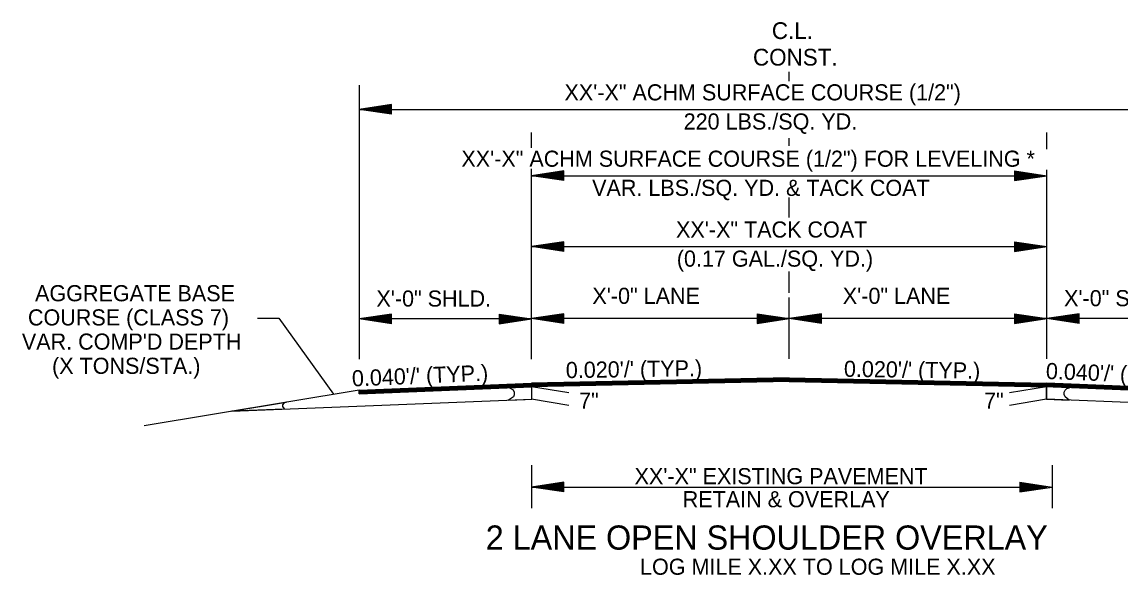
# Model space of a CAD drawing. Extents: x 542112 to 1930787, y -1968972 to 596640.
# Drawn here: x 546593 to 547104, y -1956850 to -1956593 of the extents above; entities that cross this region are included whole.
import ezdxf

# ---------------------------------------------------------------- set-up
doc = ezdxf.new("R2010")
doc.units = 0
doc.layers.add('R_Draft', color=7, linetype='Continuous')

msp = doc.modelspace()

# ---------------------------------------------------------------- linework, layer by layer
at = {"layer": 'R_Draft'}
for p, q in [((546950.47, -1956620.68), (546950.47, -1956616.27)), ((546750.21, -1956622.52), (546750.21, -1956749.95)), ((546765.21, -1956631.53), (546750.21, -1956633.78)), ((546765.21, -1956631.91), (546752.71, -1956633.78)), ((546765.21, -1956632.29), (546755.29, -1956633.78)), ((546765.21, -1956632.66), (546757.79, -1956633.78)), ((546765.21, -1956636.03), (546765.21, -1956631.53)), ((546750.21, -1956633.78), (547150.66, -1956633.78)), ((546765.21, -1956636.03), (546750.21, -1956633.78)), ((546765.21, -1956635.66), (546752.71, -1956633.78)), ((546765.21, -1956635.27), (546755.29, -1956633.78)), ((546765.21, -1956634.9), (546757.79, -1956633.78)), ((546765.21, -1956633.05), (546760.33, -1956633.78)), ((546765.21, -1956634.51), (546760.33, -1956633.78)), ((546765.21, -1956633.43), (546762.84, -1956633.78)), ((546765.21, -1956634.13), (546762.84, -1956633.78)), ((546830.47, -1956651.76), (546830.47, -1956644.62)), ((546950.47, -1956650.81), (546950.47, -1956647.14)), ((547070.4, -1956652.27), (547070.4, -1956644.62)), ((546830.47, -1956749.95), (546830.47, -1956661.53)), ((546845.47, -1956662.4), (546830.47, -1956664.65)), ((546845.47, -1956662.78), (546832.98, -1956664.65)), ((546845.47, -1956663.16), (546835.56, -1956664.65)), ((546845.47, -1956663.53), (546838.05, -1956664.65)), ((546845.47, -1956666.9), (546845.47, -1956662.4)), ((547055.4, -1956662.4), (547070.4, -1956664.65)), ((547055.4, -1956662.4), (547055.4, -1956666.9)), ((547055.4, -1956662.78), (547067.89, -1956664.65)), ((547055.4, -1956663.16), (547065.31, -1956664.65)), ((547055.4, -1956663.53), (547062.81, -1956664.65)), ((547070.4, -1956749.78), (547070.4, -1956661.94)), ((546830.47, -1956664.65), (547070.4, -1956664.65)), ((546845.47, -1956666.9), (546830.47, -1956664.65)), ((546845.47, -1956666.53), (546832.98, -1956664.65)), ((546845.47, -1956666.14), (546835.56, -1956664.65)), ((546845.47, -1956665.77), (546838.05, -1956664.65)), ((546845.47, -1956663.92), (546840.6, -1956664.65)), ((546845.47, -1956665.38), (546840.6, -1956664.65)), ((546845.47, -1956664.3), (546843.1, -1956664.65)), ((546845.47, -1956665), (546843.1, -1956664.65)), ((547055.4, -1956663.92), (547060.27, -1956664.65)), ((547055.4, -1956664.3), (547057.77, -1956664.65)), ((547055.4, -1956666.9), (547070.4, -1956664.65)), ((547055.4, -1956665.39), (547060.27, -1956664.65)), ((547055.4, -1956666.14), (547065.31, -1956664.65)), ((547055.4, -1956666.53), (547067.89, -1956664.65)), ((547055.4, -1956665.77), (547062.81, -1956664.65)), ((547055.4, -1956665), (547057.77, -1956664.65)), ((546950.47, -1956684.16), (546950.47, -1956674.86)), ((546845.47, -1956695.33), (546830.47, -1956697.58)), ((546830.47, -1956697.58), (547070.4, -1956697.58)), ((546845.47, -1956699.83), (546830.47, -1956697.58)), ((546845.47, -1956695.71), (546832.98, -1956697.58)), ((546845.47, -1956699.46), (546832.98, -1956697.58)), ((546845.47, -1956696.09), (546835.56, -1956697.58)), ((546845.47, -1956699.07), (546835.56, -1956697.58)), ((546845.47, -1956696.46), (546838.05, -1956697.58)), ((546845.47, -1956698.7), (546838.05, -1956697.58)), ((546845.47, -1956696.85), (546840.6, -1956697.58)), ((546845.47, -1956698.31), (546840.6, -1956697.58)), ((546845.47, -1956697.23), (546843.1, -1956697.58)), ((546845.47, -1956697.93), (546843.1, -1956697.58)), ((546845.47, -1956699.83), (546845.47, -1956695.33)), ((547055.4, -1956695.33), (547070.4, -1956697.58)), ((547055.4, -1956695.33), (547055.4, -1956699.83)), ((547055.4, -1956695.71), (547067.89, -1956697.58)), ((547055.4, -1956696.09), (547065.31, -1956697.58)), ((547055.4, -1956696.46), (547062.81, -1956697.58)), ((547055.4, -1956696.85), (547060.27, -1956697.58)), ((547055.4, -1956697.23), (547057.77, -1956697.58)), ((547055.4, -1956699.83), (547070.4, -1956697.58)), ((547055.4, -1956698.32), (547060.27, -1956697.58)), ((547055.4, -1956699.07), (547065.31, -1956697.58)), ((547055.4, -1956699.46), (547067.89, -1956697.58)), ((547055.4, -1956698.7), (547062.81, -1956697.58)), ((547055.4, -1956697.93), (547057.77, -1956697.58)), ((546950.47, -1956719.1), (546950.47, -1956709.23)), ((546830.47, -1956749.78), (546830.47, -1956721.23)), ((546950.47, -1956749.78), (546950.47, -1956721.23)), ((547070.4, -1956731.12), (547070.4, -1956721.23)), ((546765.21, -1956729.04), (546750.21, -1956731.29)), ((546765.21, -1956729.41), (546752.71, -1956731.29)), ((546765.21, -1956729.8), (546755.29, -1956731.29)), ((546765.21, -1956733.54), (546765.21, -1956729.04)), ((546815.47, -1956729.04), (546830.47, -1956731.29)), ((546815.47, -1956729.04), (546815.47, -1956733.54)), ((546815.47, -1956729.41), (546827.97, -1956731.29)), ((546815.47, -1956729.8), (546825.39, -1956731.29)), ((546845.47, -1956728.87), (546830.47, -1956731.12)), ((546845.47, -1956729.24), (546832.98, -1956731.12)), ((546845.47, -1956729.63), (546835.56, -1956731.12)), ((546845.47, -1956730), (546838.05, -1956731.12)), ((546845.47, -1956733.37), (546845.47, -1956728.87)), ((546935.47, -1956728.87), (546950.47, -1956731.12)), ((546935.47, -1956728.87), (546935.47, -1956733.37)), ((546935.47, -1956729.24), (546947.97, -1956731.12)), ((546935.47, -1956729.63), (546945.39, -1956731.12)), ((546935.47, -1956730), (546942.89, -1956731.12)), ((546965.47, -1956728.87), (546950.47, -1956731.12)), ((546965.47, -1956729.24), (546952.98, -1956731.12)), ((546965.47, -1956729.63), (546955.56, -1956731.12)), ((546965.47, -1956730), (546958.05, -1956731.12)), ((546965.47, -1956733.37), (546965.47, -1956728.87)), ((547055.4, -1956728.87), (547070.4, -1956731.12)), ((547055.4, -1956728.87), (547055.4, -1956733.37)), ((547055.4, -1956729.24), (547067.89, -1956731.12)), ((547055.4, -1956729.63), (547065.31, -1956731.12)), ((547055.4, -1956730), (547062.81, -1956731.12)), ((547085.4, -1956728.87), (547070.4, -1956731.12)), ((547085.4, -1956729.24), (547072.9, -1956731.12)), ((547085.4, -1956729.63), (547075.48, -1956731.12)), ((547085.4, -1956730), (547077.98, -1956731.12)), ((547085.4, -1956733.37), (547085.4, -1956728.87)), ((546830.47, -1956731.29), (546750.21, -1956731.29)), ((546765.21, -1956733.54), (546750.21, -1956731.29)), ((546765.21, -1956733.16), (546752.71, -1956731.29)), ((546765.21, -1956732.78), (546755.29, -1956731.29)), ((546765.21, -1956730.17), (546757.79, -1956731.29)), ((546765.21, -1956732.41), (546757.79, -1956731.29)), ((546765.21, -1956730.55), (546760.33, -1956731.29)), ((546765.21, -1956732.02), (546760.33, -1956731.29)), ((546765.21, -1956730.94), (546762.84, -1956731.29)), ((546765.21, -1956731.64), (546762.84, -1956731.29)), ((546815.47, -1956730.17), (546822.89, -1956731.29)), ((546815.47, -1956730.56), (546820.35, -1956731.29)), ((546815.47, -1956730.94), (546817.84, -1956731.29)), ((546815.47, -1956733.54), (546830.47, -1956731.29)), ((546815.47, -1956732.02), (546820.35, -1956731.29)), ((546815.47, -1956732.78), (546825.39, -1956731.29)), ((546815.47, -1956733.16), (546827.97, -1956731.29)), ((546815.47, -1956732.41), (546822.89, -1956731.29)), ((546815.47, -1956731.64), (546817.84, -1956731.29)), ((546950.47, -1956731.12), (546830.47, -1956731.12)), ((546845.47, -1956733.37), (546830.47, -1956731.12)), ((546845.47, -1956732.99), (546832.98, -1956731.12)), ((546845.47, -1956732.61), (546835.56, -1956731.12)), ((546845.47, -1956732.24), (546838.05, -1956731.12)), ((546845.47, -1956730.38), (546840.6, -1956731.12)), ((546845.47, -1956731.85), (546840.6, -1956731.12)), ((546845.47, -1956730.77), (546843.1, -1956731.12)), ((546845.47, -1956731.47), (546843.1, -1956731.12)), ((546935.47, -1956730.39), (546940.35, -1956731.12)), ((546935.47, -1956730.77), (546937.84, -1956731.12)), ((546935.47, -1956733.37), (546950.47, -1956731.12)), ((546935.47, -1956731.85), (546940.35, -1956731.12)), ((546935.47, -1956732.61), (546945.39, -1956731.12)), ((546935.47, -1956732.99), (546947.97, -1956731.12)), ((546935.47, -1956732.24), (546942.89, -1956731.12)), ((546935.47, -1956731.47), (546937.84, -1956731.12)), ((547070.4, -1956731.12), (546950.47, -1956731.12)), ((546965.47, -1956733.37), (546950.47, -1956731.12)), ((546965.47, -1956732.99), (546952.98, -1956731.12)), ((546965.47, -1956732.61), (546955.56, -1956731.12)), ((546965.47, -1956732.24), (546958.05, -1956731.12)), ((546965.47, -1956730.38), (546960.6, -1956731.12)), ((546965.47, -1956731.85), (546960.6, -1956731.12)), ((546965.47, -1956730.77), (546963.1, -1956731.12)), ((546965.47, -1956731.47), (546963.1, -1956731.12)), ((547055.4, -1956730.39), (547060.27, -1956731.12)), ((547055.4, -1956730.77), (547057.77, -1956731.12)), ((547055.4, -1956733.37), (547070.4, -1956731.12)), ((547055.4, -1956731.85), (547060.27, -1956731.12)), ((547055.4, -1956732.61), (547065.31, -1956731.12)), ((547055.4, -1956732.99), (547067.89, -1956731.12)), ((547055.4, -1956732.24), (547062.81, -1956731.12)), ((547055.4, -1956731.47), (547057.77, -1956731.12)), ((547070.4, -1956749.78), (547070.4, -1956731.12)), ((547150.66, -1956731.12), (547070.4, -1956731.12)), ((547085.4, -1956733.37), (547070.4, -1956731.12)), ((547085.4, -1956732.99), (547072.9, -1956731.12)), ((547085.4, -1956732.61), (547075.48, -1956731.12)), ((547085.4, -1956732.24), (547077.98, -1956731.12)), ((547085.4, -1956730.38), (547080.52, -1956731.12)), ((547085.4, -1956731.85), (547080.52, -1956731.12)), ((547085.4, -1956730.77), (547083.03, -1956731.12)), ((547085.4, -1956731.47), (547083.03, -1956731.12)), ((546950.47, -1956758.72), (546830.47, -1956761.12)), ((546950.48, -1956759.02), (546830.48, -1956761.42)), ((546950.48, -1956759.32), (546830.48, -1956761.72)), ((546950.49, -1956759.62), (546830.49, -1956762.02)), ((546950.49, -1956759.92), (546830.49, -1956762.32)), ((546950.5, -1956760.22), (546830.5, -1956762.62)), ((546950.5, -1956760.42), (546830.5, -1956762.82)), ((546950.44, -1956760.22), (547070.44, -1956762.62)), ((546950.44, -1956760.42), (547070.44, -1956762.82)), ((546950.45, -1956759.62), (547070.45, -1956762.02)), ((546950.45, -1956759.92), (547070.45, -1956762.32)), ((546950.46, -1956759.02), (547070.46, -1956761.42)), ((546950.46, -1956759.32), (547070.46, -1956761.72)), ((546950.47, -1956758.72), (547070.47, -1956761.12)), ((546750.21, -1956764.33), (546650.14, -1956781.01)), ((546750.21, -1956764.33), (546830.47, -1956761.12)), ((546750.21, -1956764.63), (546830.48, -1956761.42)), ((546750.21, -1956764.93), (546830.49, -1956761.72)), ((546750.21, -1956765.24), (546830.51, -1956762.02)), ((546750.21, -1956765.54), (546830.52, -1956762.32)), ((546750.21, -1956765.84), (546830.53, -1956762.62)), ((546750.21, -1956766.04), (546830.54, -1956762.82)), ((546750.21, -1956766.03), (546750.21, -1956764.33)), ((546750.21, -1956766.04), (546750.21, -1956764.33)), ((546847.8, -1956765.71), (546830.5, -1956762.82)), ((546830.61, -1956768.62), (546830.61, -1956762.82)), ((547070.33, -1956762.82), (547053.04, -1956765.7)), ((547070.33, -1956768.62), (547070.33, -1956762.82)), ((547073.36, -1956762.94), (547070.33, -1956762.82)), ((547150.73, -1956766.04), (547070.4, -1956762.82)), ((547150.73, -1956765.84), (547070.41, -1956762.62)), ((547150.73, -1956765.54), (547070.42, -1956762.32)), ((547150.73, -1956765.24), (547070.43, -1956762.02)), ((547150.73, -1956764.93), (547070.45, -1956761.72)), ((547150.73, -1956764.63), (547070.46, -1956761.42)), ((547150.73, -1956764.33), (547070.47, -1956761.12)), ((547080.91, -1956763.24), (547073.36, -1956762.94)), ((546690.99, -1956774.2), (546830.61, -1956768.62)), ((546690.99, -1956774.2), (546716.16, -1956770.01)), ((546819.7, -1956769.06), (546827.58, -1956768.74)), ((546827.58, -1956768.74), (546830.61, -1956768.62)), ((546847.8, -1956771.5), (546830.5, -1956768.62)), ((547070.33, -1956768.62), (547053.04, -1956771.5)), ((547209.96, -1956774.2), (547070.33, -1956768.62)), ((546711.13, -1956773.37), (546690.99, -1956774.2)), ((546715.4, -1956773.23), (546711.13, -1956773.37)), ((546830.47, -1956799.21), (546830.47, -1956819.21)), ((547072.9, -1956799.21), (547072.9, -1956819.21)), ((546845.47, -1956807.21), (546830.47, -1956809.46)), ((546830.47, -1956809.46), (547070.4, -1956809.46)), ((546845.47, -1956811.71), (546830.47, -1956809.46)), ((546845.47, -1956807.59), (546832.98, -1956809.46)), ((546845.47, -1956811.34), (546832.98, -1956809.46)), ((546845.47, -1956807.97), (546835.56, -1956809.46)), ((546845.47, -1956810.96), (546835.56, -1956809.46)), ((546845.47, -1956808.35), (546838.05, -1956809.46)), ((546845.47, -1956810.58), (546838.05, -1956809.46)), ((546845.47, -1956808.73), (546840.6, -1956809.46)), ((546845.47, -1956810.19), (546840.6, -1956809.46)), ((546845.47, -1956809.11), (546843.1, -1956809.46)), ((546845.47, -1956809.82), (546843.1, -1956809.46)), ((546845.47, -1956811.71), (546845.47, -1956807.21)), ((547057.9, -1956807.21), (547072.9, -1956809.46)), ((547057.9, -1956807.21), (547057.9, -1956811.71)), ((547057.9, -1956807.59), (547070.4, -1956809.46)), ((547057.9, -1956807.97), (547067.82, -1956809.46)), ((547057.9, -1956808.35), (547065.32, -1956809.46)), ((547057.9, -1956808.74), (547062.78, -1956809.46)), ((547057.9, -1956809.11), (547060.27, -1956809.46)), ((547057.9, -1956811.71), (547072.9, -1956809.46)), ((547057.9, -1956810.2), (547062.78, -1956809.46)), ((547057.9, -1956810.96), (547067.82, -1956809.46)), ((547057.9, -1956811.34), (547070.4, -1956809.46)), ((547057.9, -1956810.58), (547065.32, -1956809.46)), ((547057.9, -1956809.82), (547060.27, -1956809.46))]:
    msp.add_line(p, q, dxfattribs=at)
for points in [[(546702.81, -1956730.87), (546712.81, -1956730.87), (546738.28, -1956766.32)], [(546820.18, -1956763.24), (546821.86, -1956764.25), (546822.32, -1956765.28), (546822.36, -1956766.5), (546822.01, -1956767.46), (546821.18, -1956768.16), (546819.7, -1956769.06)], [(546830.61, -1956768.62), (546830.61, -1956762.82), (546820.18, -1956763.24)], [(547070.33, -1956762.82), (547070.33, -1956768.62), (547080.83, -1956769.04)], [(547080.83, -1956769.04), (547078.9, -1956767.53), (547078.48, -1956766.49), (547078.49, -1956765.26), (547078.88, -1956764.33), (547079.74, -1956763.65), (547080.91, -1956763.24)], [(546716.16, -1956770.01), (546715.09, -1956770.48), (546714.58, -1956771.24), (546714.5, -1956771.96), (546714.75, -1956772.49), (546715.4, -1956773.23)]]:
    msp.add_lwpolyline(points, dxfattribs=at)

# ---------------------------------------------------------------- texts
for s, height, p in [('C.L.', 7.8, (546942.37, -1956601.07)), ('CONST.', 7.8, (546933.58, -1956613.43)), ('XX\'-X" ACHM SURFACE COURSE (1/2")', 7.5, (546845.81, -1956629.62)), ('220 LBS./SQ. YD. ', 7.5, (546901.3, -1956643.16)), ('XX\'-X" ACHM SURFACE COURSE (1/2") FOR LEVELING *', 7.5, (546797.8, -1956660.49)), ('VAR. LBS./SQ. YD. & TACK COAT', 7.5, (546858.69, -1956674.03)), ('XX\'-X" TACK COAT', 7.5, (546897.75, -1956693.41)), ('(0.17 GAL./SQ. YD.)', 7.5, (546898.11, -1956706.96)), ('AGGREGATE BASE', 7.5, (546599.3, -1956723.06)), ('X\'-0" SHLD.', 7.5, (546758.24, -1956725.52)), ('X\'-0" LANE', 7.5, (546858.81, -1956724.26)), ('X\'-0" LANE', 7.5, (546975.4, -1956724.26)), ('X\'-0" SHLD.', 7.5, (547078.43, -1956725.35)), ('COURSE (CLASS 7)', 7.5, (546595.99, -1956734.31)), ("VAR. COMP'D DEPTH", 7.5, (546593.16, -1956745.56)), ('(X TONS/STA.)', 7.5, (546607.21, -1956756.81)), ('7"', 7.5, (546852.63, -1956772.99)), ('7"', 7.5, (547041.19, -1956772.99)), ('XX\'-X" EXISTING PAVEMENT', 7.5, (546878.45, -1956808.14)), ('RETAIN & OVERLAY', 7.5, (546900.86, -1956818.86)), ('2 LANE OPEN SHOULDER OVERLAY', 11.25, (546809.14, -1956838.58)), ('LOG MILE X.XX TO LOG MILE X.XX', 7.5, (546880.99, -1956850.27))]:
    msp.add_text(s, height=height, dxfattribs=at).set_placement(p)
for s, rotation, p in [("0.020'/' (TYP.)", 0.8719, (546846.48, -1956758.82)), ("0.040'/' (TYP.)", 2.448, (546747, -1956762.7)), ("0.020'/' (TYP.)", 359.164, (546975.89, -1956758.17)), ("0.040'/' (TYP.) ", 357.8168, (547069.86, -1956759.17))]:
    msp.add_text(s, height=7.5, rotation=rotation, dxfattribs=at).set_placement(p)

doc.saveas('drawing.dxf')
